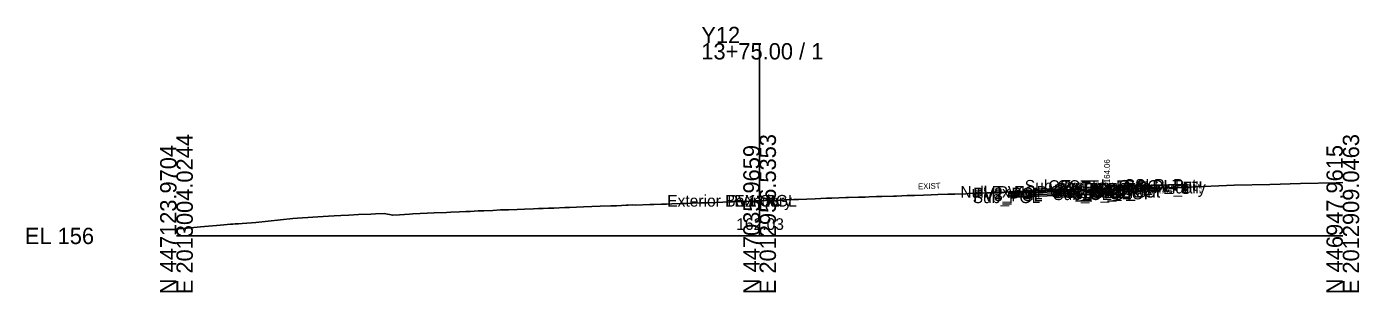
# Model space of a CAD drawing. Extents: x -26 to 1203, y -10 to 9542.
# Drawn here: x -25.7 to 202.8, y 7490.3 to 7535.9 of the extents above; entities that cross this region are included whole.
import ezdxf

# ---------------------------------------------------------------- set-up
doc = ezdxf.new("R2010")
doc.units = 0
for name, color, linetype in [('Default', 7, 'Continuous'), ('Exist Cross Section Cell', 7, 'Continuous'), ('Exist XS Center Line Elevation Label', 7, 'Continuous'), ('Exist XS Ground Line', 7, 'Continuous'), ('Prop CMT Conc Surface', 7, 'Continuous'), ('Prop CMT Concrete Structures', 7, 'Continuous'), ('Prop CMT Pvmt Course 1', 7, 'Continuous'), ('Prop CMT Pvmt Course 1 CG', 7, 'Continuous'), ('Prop CMT Pvmt Course 2', 7, 'Continuous'), ('Prop CMT Pvmt Course 3', 7, 'Continuous'), ('Prop CMT Pvmt Surface', 7, 'Continuous'), ('Prop CMT Slope Grass', 7, 'Continuous'), ('Prop CMT Subgrade Earthwork', 7, 'Continuous'), ('Prop XS Earthwork Shape', 7, 'Continuous'), ('Prop XS Finish Grade CurbGutter', 7, 'Continuous'), ('Prop XS Hydro Elevations', 7, 'Continuous'), ('Prop XS SE Text', 7, 'Continuous'), ('Scratch_Level_0', 7, 'Continuous')]:
    doc.layers.add(name, color=color, linetype=linetype)

msp = doc.modelspace()

# ---------------------------------------------------------------- linework, layer by layer
at = {"layer": 'Exist Cross Section Cell'}
for p, q in [((100, 7500), (100, 7533.09)), ((0, 7500), (100, 7500)), ((100, 7500), (200, 7500))]:
    msp.add_line(p, q, dxfattribs=at)
at = {"layer": 'Exist XS Ground Line'}
msp.add_lwpolyline([(0, 7501.16), (0.42, 7501.2), (1.21, 7501.27), (1.86, 7501.33), (2.43, 7501.38), (2.97, 7501.43), (3.55, 7501.48), (4.11, 7501.53), (6.84, 7501.79), (7.49, 7501.85), (8.1, 7501.91), (8.71, 7501.95), (9.24, 7501.99), (9.65, 7502.02), (10.05, 7502.05), (10.61, 7502.09), (11.28, 7502.14), (12.04, 7502.19), (12.84, 7502.24), (13.63, 7502.29), (19.98, 7503), (20.74, 7503.04), (21.6, 7503.09), (22.5, 7503.15), (23.37, 7503.2), (24.25, 7503.25), (25.14, 7503.31), (26.08, 7503.37), (27.05, 7503.43), (28.16, 7503.49), (29.54, 7503.57), (31.24, 7503.66), (33.33, 7503.76), (34.14, 7503.8), (35.61, 7503.87), (37.08, 7503.55), (38.23, 7503.64), (39.95, 7503.74), (40.54, 7503.77), (41.77, 7503.84), (44.2, 7503.96), (46.32, 7504.04), (47.03, 7504.07), (48.56, 7504.13), (49.64, 7504.18), (50.36, 7504.21), (51.71, 7504.28), (52.35, 7504.3), (52.7, 7504.32), (54.22, 7504.39), (55.57, 7504.45), (56.96, 7504.5), (58.41, 7504.55), (59.69, 7504.58), (61.21, 7504.64), (62.1, 7504.68), (62.86, 7504.71), (63.82, 7504.74), (64.12, 7504.76), (64.73, 7504.78), (66.61, 7504.85), (67.1, 7504.87), (67.42, 7504.88), (69.78, 7504.98), (72.64, 7505.08), (74.47, 7505.15), (75.47, 7505.19), (76.33, 7505.22), (77.11, 7505.25), (77.45, 7505.28), (78.17, 7505.31), (78.72, 7505.3), (81.16, 7505.37), (81.88, 7505.4), (83.2, 7505.44), (84.01, 7505.46), (84.95, 7505.5), (86.84, 7505.56), (87.4, 7505.58), (88.45, 7505.62), (89.66, 7505.66), (91.08, 7505.7), (92.48, 7505.74), (93.7, 7505.79), (94.75, 7505.84), (95.32, 7505.86), (96.6, 7505.9), (98.17, 7505.96), (98.63, 7505.98), (99.36, 7506), (100.16, 7506.03), (101, 7506.06), (103.42, 7506.15), (103.84, 7506.16), (104.19, 7506.18), (105.81, 7506.24), (106.68, 7506.27), (109.53, 7506.38), (111.45, 7506.47), (112.4, 7506.5), (114.78, 7506.57), (115.26, 7506.58), (116.93, 7506.63), (118.08, 7506.67), (118.77, 7506.7), (120.05, 7506.74), (120.63, 7506.76), (120.94, 7506.77), (122.95, 7506.84), (123.47, 7506.85), (125.29, 7506.91), (126.58, 7506.96), (128.1, 7507.01), (129.42, 7507.06), (130.53, 7507.1), (132.26, 7507.15), (133.5, 7507.18), (135.37, 7507.24), (135.83, 7507.26), (137.94, 7507.35), (139.02, 7507.38), (140.86, 7507.42), (142.84, 7507.55), (143.45, 7507.54), (145.27, 7507.54), (147.78, 7508.03), (148.45, 7508.06), (149.26, 7508.06), (150.64, 7508), (151.63, 7507.95), (152.06, 7507.76), (152.62, 7507.7), (153.44, 7507.7), (155.2, 7507.74), (159.98, 7507.93), (167.58, 7508.19), (173.4, 7508.35), (181.38, 7508.7), (187.47, 7508.84), (192.73, 7508.99), (198.84, 7509.14), (200, 7509.18)], dxfattribs=at)
at = {"layer": 'Prop CMT Conc Surface'}
msp.add_lwpolyline([(157.56, 7508.07), (159.56, 7508.06), (159.56, 7508.56), (160.06, 7508.56)], dxfattribs=at)
at = {"layer": 'Prop CMT Concrete Structures'}
for points in [[(157.56, 7508.07), (159.56, 7508.06), (159.56, 7508.56), (160.06, 7508.56)], [(160.06, 7508.56), (160.06, 7507.57), (157.56, 7507.48)], [(157.56, 7507.48), (157.56, 7508.07)]]:
    msp.add_lwpolyline(points, dxfattribs=at)
at = {"layer": 'Prop CMT Pvmt Course 1'}
for points in [[(142.72, 7507.54), (157.56, 7508.07)], [(157.56, 7507.82), (142.72, 7507.29)], [(142.72, 7507.54), (142.72, 7507.54)], [(142.72, 7507.29), (142.72, 7507.54)], [(157.56, 7508.07), (157.56, 7507.82)], [(100, 7506.03), (100, 7506.03)]]:
    msp.add_lwpolyline(points, dxfattribs=at)
at = {"layer": 'Prop CMT Pvmt Course 1 CG'}
for points in [[(157.56, 7507.48), (160.56, 7507.59), (160.88, 7507.27)], [(157.56, 7507.15), (157.56, 7507.48)], [(160.88, 7507.27), (157.56, 7507.15)]]:
    msp.add_lwpolyline(points, dxfattribs=at)
at = {"layer": 'Prop CMT Pvmt Course 2'}
for points in [[(142.72, 7507.29), (157.56, 7507.82)], [(157.56, 7507.48), (142.72, 7506.96)], [(157.56, 7507.82), (157.56, 7507.48)], [(142.72, 7506.96), (142.72, 7507.29)]]:
    msp.add_lwpolyline(points, dxfattribs=at)
at = {"layer": 'Prop CMT Pvmt Course 3'}
for points in [[(142.72, 7506.96), (157.56, 7507.48)], [(157.56, 7507.48), (157.56, 7507.15)], [(157.56, 7507.15), (142.72, 7506.63)], [(142.72, 7506.63), (142.72, 7506.96)]]:
    msp.add_lwpolyline(points, dxfattribs=at)
at = {"layer": 'Prop CMT Pvmt Surface'}
msp.add_lwpolyline([(142.72, 7507.54), (157.56, 7508.07)], dxfattribs=at)
at = {"layer": 'Prop CMT Slope Grass'}
msp.add_line((160.06, 7508.56), (172.72, 7508.81), dxfattribs=at)
msp.add_lwpolyline([(172.72, 7508.81), (172.72, 7507.35), (173.39, 7507.35), (173.39, 7508.35)], dxfattribs=at)
at = {"layer": 'Prop CMT Subgrade Earthwork'}
for points in [[(142.72, 7506.63), (142.72, 7507.54)], [(157.56, 7507.15), (160.88, 7507.27), (162.22, 7508.6)], [(142.72, 7506.63), (157.56, 7507.15)], [(157.56, 7507.15), (142.72, 7506.63)]]:
    msp.add_lwpolyline(points, dxfattribs=at)
at = {"layer": 'Prop XS Earthwork Shape'}
for points in [[(160.06, 7507.93), (160.06, 7507.57), (157.56, 7507.48), (157.56, 7507.83), (155.2, 7507.74), (153.44, 7507.7), (152.62, 7507.7), (152.06, 7507.76), (151.83, 7507.86), (145.86, 7507.65), (145.27, 7507.54), (143.45, 7507.54), (142.84, 7507.55), (142.72, 7507.54), (142.72, 7506.63), (157.56, 7507.15), (160.88, 7507.27), (161.6, 7507.98)], [(151.63, 7507.95), (151.83, 7507.86), (145.86, 7507.65), (147.78, 7508.03), (148.45, 7508.06), (149.26, 7508.06), (150.64, 7508)], [(160.06, 7507.93), (160.06, 7507.57), (157.56, 7507.48), (157.56, 7507.83), (159.98, 7507.93)], [(162.22, 7508.6), (172.72, 7508.81), (172.72, 7508.33), (167.58, 7508.19), (161.6, 7507.98)], [(173.39, 7507.35), (173.39, 7508.35), (172.72, 7508.33), (172.72, 7507.35)]]:
    msp.add_lwpolyline(points, close=True, dxfattribs=at)
at = {"layer": 'Prop XS Finish Grade CurbGutter'}
for p, q in [((172.72, 7508.85), (172.91, 7508.85)), ((172.72, 7508.85), (173.39, 7508.85)), ((172.72, 7508.85), (172.72, 7507.85)), ((172.72, 7507.85), (172.72, 7507.35)), ((172.72, 7507.85), (173.39, 7507.85)), ((172.72, 7507.35), (173.39, 7507.35)), ((173.39, 7508.43), (173.03, 7508.8)), ((173.39, 7508.43), (173.39, 7507.85)), ((173.39, 7508.35), (173.39, 7508.35)), ((173.39, 7507.85), (173.39, 7507.35))]:
    msp.add_line(p, q, dxfattribs=at)
msp.add_arc((172.91, 7508.68), 0.166, 43.9997, 90, dxfattribs=at)

# ---------------------------------------------------------------- texts
at = {"layer": 'Default'}
msp.add_text('-', height=0.0001, dxfattribs=at).set_placement((0, 7500))
at = {"layer": 'Exist Cross Section Cell'}
for s, p in [('Y12', (90, 7533.09)), ('13+75.00 / 1', (90, 7530.29)), ('EL 156', (-26, 7498.6))]:
    msp.add_text(s, height=2.8, dxfattribs=at).set_placement(p)
for s, p in [('E 2013004.0244', (2.8, 7490)), ('E 2012956.5353', (102.8, 7490)), ('E 2012909.0463', (202.8, 7490)), ('N 447123.9704', (0, 7490)), ('N 447035.9659', (100, 7490)), ('N 446947.9615', (200, 7490))]:
    msp.add_text(s, height=2.8, rotation=90, dxfattribs=at).set_placement(p)
at = {"layer": 'Exist XS Center Line Elevation Label'}
msp.add_text('162.03', height=2, dxfattribs=at).set_placement((95.99, 7501.03))
at = {"layer": 'Prop XS Hydro Elevations'}
msp.add_text('164.06', height=1, rotation=90, dxfattribs=at).set_placement((160.06, 7509.06))
at = {"layer": 'Prop XS SE Text'}
msp.add_text('EXIST', height=1, rotation=2.0283, dxfattribs=at).set_placement((127.17, 7507.99))
at = {"layer": 'Scratch_Level_0'}
for s, p in [('Sub_Trench_Out_DLT', (145.47, 7507.6)), ('CG_Top_Face', (149.51, 7507.56)), ('CG_Top_BOC', (151.04, 7507.56)), ('CSLP_Pnt', (162.43, 7507.75)), ('Null Ex EOP', (134.42, 7506.54)), ('Sub_PGL', (136.53, 7505.63)), ('PV2_PGL', (136.62, 7506.29)), ('PV3_PGL', (136.62, 7505.96)), ('PV1', (140.79, 7506.54)), ('CG1_Shelf_Out', (149.8, 7506.59)), ('CG_Bot_IE', (150.17, 7506.48)), ('Sub_OEOT', (150.33, 7506.15)), ('CG_Top_Gut', (150.49, 7507.06)), ('PV2_OEOT', (150.43, 7506.82)), ('PV3_OEOT', (150.43, 7506.48)), ('CG_Bot_BOC', (151.07, 7506.57)), ('PV1_OEOT', (150.99, 7507.07)), ('Sub_OEOP', (153.69, 7506.27)), ('Exterior Boundary', (155.08, 7507.29)), ('Slope_Fill', (164.15, 7507.29)), ('Exterior Boundary', (84.14, 7505.03)), ('PV1_PGL', (94.47, 7505.03)), ('EX CL', (95.67, 7505.03))]:
    msp.add_text(s, height=2, dxfattribs=at).set_placement(p)

doc.saveas('drawing.dxf')
